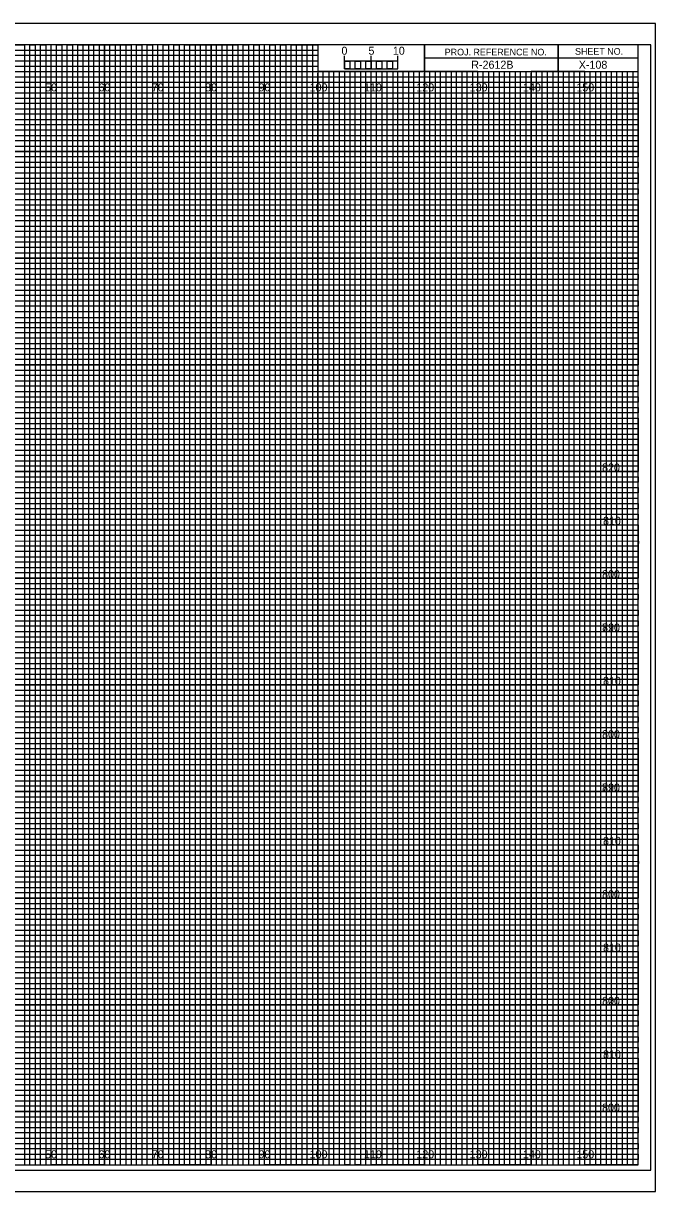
# Model space of a CAD drawing. Extents: x -13 to 323, y -5 to 214.
# Drawn here: x 204.8 to 323.3, y -5 to 214 of the extents above; entities that cross this region are included whole.
import ezdxf

# ---------------------------------------------------------------- set-up
doc = ezdxf.new("R2010")
doc.units = 0
for name, color, linetype in [('Prop XS Bar Scale Labels', 7, 'Continuous'), ('Prop XS Elevation Labels', 7, 'Continuous'), ('Prop XS Offset Labels', 7, 'Continuous'), ('Prop XS Project Number', 7, 'Continuous'), ('Prop XS Sheet Number', 7, 'Continuous'), ('Sheet Cross Section CELL', 7, 'Continuous'), ('Sheet Cross Section Grid Major CELL', 7, 'Continuous'), ('Sheet Cross Section Grid Middle CELL', 7, 'Continuous'), ('Sheet Cross Section Grid Minor 1 CELL', 7, 'Continuous'), ('Sheet Cross Section Grid Minor 2 CELL', 7, 'Continuous'), ('Sheet Cross Section Scale CELL', 7, 'Continuous'), ('Sheet Cutting Line CELL', 7, 'Continuous'), ('Sheet DOT Grid CELL', 7, 'Continuous'), ('Sheet Plot Border Inside CELL', 7, 'Continuous'), ('Sheet Plot Border Outside CELL', 7, 'Continuous')]:
    doc.layers.add(name, color=color, linetype=linetype)

msp = doc.modelspace()

# ---------------------------------------------------------------- linework, layer by layer
at = {"layer": 'Sheet Cross Section CELL'}
for p, q in [((305, 210), (305, 205)), ((305, 205), (305, 210)), ((280, 207.5), (280, 205)), ((320, 207.49), (280, 207.49)), ((280, 205), (320, 205))]:
    msp.add_line(p, q, dxfattribs=at)
for points in [[(320, 210), (0, 210), (0, 0), (320, 0)], [(280, 210), (260, 210), (260, 205.03), (280, 205.03)], [(320, 210), (280, 210), (280, 205), (320, 205)]]:
    msp.add_lwpolyline(points, close=True, dxfattribs=at)
at = {"layer": 'Sheet Cross Section Grid Major CELL'}
for p, q in [((210, 210), (200, 210)), ((210, 0), (210, 210)), ((230, 210), (220, 210)), ((220, 210), (220, 0)), ((230, 0), (230, 210)), ((250, 210), (240, 210)), ((240, 210), (240, 0)), ((250, 0), (250, 210)), ((260, 210), (260, 0)), ((270, 0), (270, 205)), ((290, 205), (280, 205)), ((280, 205), (280, 0)), ((290, 0), (290, 205)), ((310, 205), (300, 205)), ((300, 205), (300, 0)), ((310, 0), (310, 205)), ((220, 0), (210, 0)), ((240, 0), (230, 0)), ((260, 0), (250, 0)), ((280, 0), (270, 0)), ((300, 0), (290, 0)), ((320, 0), (310, 0)), ((320, 0), (320, 0))]:
    msp.add_line(p, q, dxfattribs=at)
for points in [[(0, 200), (320, 200), (320, 190), (0, 190)], [(0, 180), (320, 180), (320, 170), (0, 170)], [(0, 160), (320, 160), (320, 150), (0, 150)], [(0, 140), (320, 140), (320, 130), (0, 130)], [(0, 120), (320, 120), (320, 110), (0, 110)], [(0, 100), (320, 100), (320, 90), (0, 90)], [(0, 80), (320, 80), (320, 70), (0, 70)], [(0, 60), (320, 60), (320, 50), (0, 50)], [(0, 40), (320, 40), (320, 30), (0, 30)], [(0, 20), (320, 20), (320, 10), (0, 10)]]:
    msp.add_lwpolyline(points, dxfattribs=at)
at = {"layer": 'Sheet Cross Section Grid Middle CELL'}
for points in [[(195, 210), (205, 210), (205, 0), (215, 0), (215, 210), (225, 210), (225, 0), (235, 0), (235, 210), (245, 210), (245, 0), (255, 0), (255, 210), (259.93, 210), (260, 210), (260, 205), (264.99, 205), (264.99, 0), (275, 0), (275, 205), (285, 205), (285, 0), (295, 0), (295, 205), (305, 205), (305, 0), (315, 0), (315, 205)], [(0, 205), (275, 205)], [(0, 185), (320, 185), (320, 195), (0, 195)], [(0, 165), (320, 165), (320, 175), (0, 175)], [(0, 145), (320, 145), (320, 155), (0, 155)], [(0, 125), (320, 125), (320, 135), (0, 135)], [(0, 105), (320, 105), (320, 115), (0, 115)], [(0, 85), (320, 85), (320, 95), (0, 95)], [(0, 65), (320, 65), (320, 75), (0, 75)], [(0, 45), (320, 45), (320, 55), (0, 55)], [(0, 25), (320, 25), (320, 35), (0, 35)], [(0, 5), (320, 5), (320, 15), (0, 15)]]:
    msp.add_lwpolyline(points, dxfattribs=at)
at = {"layer": 'Sheet Cross Section Grid Minor 1 CELL'}
for p, q in [((0, 209), (260, 209)), ((260, 209), (260, 207.98)), ((260, 207.98), (0, 207.98)), ((0, 207), (260, 207)), ((260, 205.89), (0, 205.89)), ((260, 207), (260, 205.89)), ((0, 204), (320, 204))]:
    msp.add_line(p, q, dxfattribs=at)
for points in [[(0, 203), (270, 203), (320, 203), (320, 202), (0, 202)], [(0, 201), (320, 201), (320, 199), (0, 199)], [(0, 198), (320, 198), (320, 197), (0, 196.98)], [(0, 196), (320, 196), (320, 194), (0, 194)], [(0, 193), (320, 193), (320, 192), (0, 192)], [(0, 191), (320, 191), (320, 189), (0, 189)], [(0, 188), (320, 188), (320, 187), (0, 187)], [(0, 186), (320, 186), (320, 184), (0, 184)], [(0, 183), (320, 183), (320, 182), (0, 182)], [(0, 181), (320, 181), (320, 179), (0, 179)], [(0, 178), (320, 178), (320, 177), (0, 177)], [(0, 176), (320, 176), (320, 173.95), (320, 173), (320, 172), (0, 172)], [(0, 174), (320, 174), (320, 173), (0, 173)], [(0, 171), (320, 171), (320, 169), (0, 169.03)], [(0, 169.03), (320, 169), (320, 168), (0, 168)], [(0, 167), (320, 167), (320, 166), (0, 166)], [(0, 164), (320, 164), (320, 163), (0, 163)], [(0, 162), (320, 162), (320, 161), (0, 161)], [(-0.07, 158.89), (320, 158.89), (320, 157.88), (-0.07, 157.88)], [(0, 157), (320, 157), (320, 156), (0, 156)], [(0, 154), (320, 154), (320, 153), (0, 153)], [(0, 152), (320, 152), (320, 151), (0, 151)], [(0, 149), (320, 149), (320, 148), (0, 148)], [(0, 147), (320, 147), (320, 146), (0, 146)], [(0, 144), (320, 144), (320, 143), (0, 143)], [(0, 142), (320, 142), (320, 141), (0, 141)], [(0, 139), (320, 139), (319.99, 137.98), (0, 138)], [(0, 137), (320, 137), (320, 136), (0, 136)], [(0, 134), (320, 134), (320, 133), (0, 133)], [(0, 132), (320, 132), (320, 131), (0, 131)], [(0, 129), (320, 129), (320, 128), (0, 128)], [(0, 127), (320, 127), (320, 126), (0, 126)], [(0, 124), (320, 124), (320, 123), (0, 123)], [(0, 122), (320, 122), (320, 121), (0, 121)], [(0, 119), (320, 119), (320, 118), (0, 118)], [(0, 116.99), (320.07, 116.91), (320, 116), (0, 116)], [(0, 114), (320, 114), (320, 113), (0, 113)], [(0, 112), (320, 112), (320, 111), (0, 111)], [(0, 109), (320, 109), (320, 108), (0, 108)], [(0, 107), (320, 107), (320, 106), (0, 106)], [(0, 104), (320, 104), (320, 103), (0, 103)], [(0, 102), (320, 102), (320, 101), (0, 101)], [(0, 99), (320, 99), (320, 98), (0, 98)], [(0, 97), (320, 97), (320, 96), (0, 96)], [(0, 94), (320, 94), (320, 93), (0, 93)], [(0, 92), (320, 92), (320, 91), (0, 91)], [(0, 89), (320, 89), (320, 88), (0, 88)], [(0, 87), (320, 87), (320, 86), (0, 86)], [(0, 84), (320, 84), (320, 83), (0, 83)], [(0, 82), (320, 82), (320, 81), (0, 81)], [(0, 79), (320, 79), (319.99, 77.98), (0, 78)], [(0, 77), (320, 77), (320, 76), (0, 76)], [(0, 74), (320, 74), (320, 73), (0, 73)], [(0, 72), (320, 72), (320, 71), (0, 71)], [(0, 69), (320, 69), (320, 68), (0, 68)], [(0, 67), (320, 67), (320, 66), (0, 66)], [(0, 64), (320, 64), (320, 63), (0, 63)], [(0, 62), (320, 62), (320, 61), (0, 61)], [(0, 59), (320, 59), (320, 58), (0, 58)], [(0, 56.99), (320.07, 56.91), (320, 56), (0, 56)], [(0, 54), (320, 54), (320, 53), (0, 53)], [(0, 52), (320, 52), (320, 51), (0, 51)], [(0, 49), (320, 49), (320, 48), (0, 48)], [(0, 47), (320, 47), (320, 46), (0, 46)], [(0, 44), (320, 44), (320, 43), (0, 43)], [(0, 42), (320, 42), (320, 41), (0, 41)], [(0, 39), (320, 39), (320, 38), (0, 38)], [(0, 37), (320, 37), (320, 36), (0, 36)], [(0, 34), (320, 34), (320, 33), (0, 33)], [(0, 32), (320, 32), (320, 31), (0, 31)], [(0, 29), (320, 29), (320, 28), (0, 28)], [(0, 27), (320, 27), (320, 26), (0, 26)], [(0, 24), (320, 24), (320, 23), (0, 23)], [(0, 22), (320, 22), (320, 21), (0, 21)], [(0, 19), (320, 19), (320, 18), (0, 18)], [(0, 17), (320, 17), (320, 16), (0, 16)], [(0, 14), (320, 14), (320, 13), (0, 13)], [(0, 12), (320, 12), (320, 11), (0, 11)], [(0, 9), (320, 9), (320, 8), (0, 8)], [(0, 7), (320, 7), (320, 6), (0, 6)], [(0, 4), (320, 4), (320, 3), (0, 3)], [(0, 2), (320, 2), (320, 1), (0, 1)]]:
    msp.add_lwpolyline(points, dxfattribs=at)
at = {"layer": 'Sheet Cross Section Grid Minor 2 CELL'}
for p, q in [((267, 205), (266.01, 205)), ((266.01, 205), (266.01, 0)), ((267, 0), (267, 205)), ((269, 205), (268, 205)), ((268, 205), (268, 0)), ((269, 0), (269, 205)), ((266.01, 0), (265, 0)), ((268, 0), (267, 0))]:
    msp.add_line(p, q, dxfattribs=at)
for points in [[(205, 0), (206, 0), (206, 210), (207, 210), (207, 0)], [(207, 0), (208, 0), (208, 210), (209, 210), (209, 0)], [(210, 0), (211, 0), (211, 210), (212, 210), (212, 0)], [(212, 0), (213, 0), (213, 210), (214, 210), (214, 0)], [(215, 0), (216, 0), (216, 210), (217, 210), (217, 0)], [(217, 0), (218, 0), (218, 210), (219, 210), (219, 0)], [(220, 0), (221, 0), (221, 210), (222, 210), (222, 0)], [(222, 0), (223, 0), (223, 210), (224, 210), (224, 0)], [(225, 0), (226, 0), (226, 210), (227, 210), (227, 0)], [(227, 0), (228, 0), (228, 210), (229, 210), (229, 0)], [(230, 0), (231, 0), (231, 210), (232, 210), (232, 0)], [(232, 0), (233, 0), (233, 210), (234, 210), (234, 0)], [(235, 0), (236, 0), (236, 210), (237, 210), (237, 0)], [(237, 0), (238, 0), (238, 210), (239, 210), (239, 0)], [(240, 0), (241, 0), (241, 210), (242, 210), (242, 0)], [(242, 0), (243, 0), (243, 210), (244, 210), (244, 0)], [(245, 0), (246, 0), (246, 210), (247, 210), (247, 0)], [(247, 0), (248, 0), (248, 210), (249, 210), (249, 0)], [(250, 0), (251, 0), (251, 210), (252, 210), (252, 0)], [(252, 0), (253, 0), (253, 210), (254, 210), (254, 0)], [(255, 0), (256, 0), (256, 210), (257, 210), (257, 0)], [(257, 0), (258, 0), (258, 210), (259, 210), (259, 0)], [(260, 0), (261, 0), (261, 205), (262.02, 205), (262.02, 0)], [(262, 0), (263, 0), (263, 205), (263.99, 205), (263.99, 0)], [(270, 0), (270.98, 0), (270.98, 205), (272, 205), (272, 0)], [(272, 0), (273, 0), (273, 205), (274.05, 205), (274.05, 0)], [(275, 0), (276, 0), (276, 205), (277, 205), (277, 0)], [(277, 0), (278, 0), (278, 205), (279, 205), (279, 0)], [(280, 0), (281, 0), (281, 205), (282, 205), (282, 0)], [(282, 0), (283, 0), (283, 205), (284, 205), (284, 0)], [(285, 0), (286, 0), (286, 205), (287, 205), (287, 0)], [(287, 0), (288, 0), (288, 205), (289, 205), (289, 0)], [(290, 0), (291, 0), (291, 205), (292, 205), (292, 0)], [(292, 0), (293, 0), (293, 205), (294, 205), (294, 0)], [(295, 0), (296, 0), (296, 205), (297, 205), (297, 0)], [(297, 0), (298, 0), (298, 205), (299, 205), (299, 0)], [(300, 0), (301, 0), (301, 205), (302, 205), (302, 0)], [(302, 0), (303, 0), (303, 205), (304, 205), (304, 0)], [(305, 0), (306, 0), (306, 205), (307, 205), (307, 0)], [(307, 0), (308, 0), (308, 205), (309, 205), (309, 0)], [(310, 0), (311, 0), (311, 205), (312, 205), (312, 0)], [(312, 0), (313, 0), (313, 205), (314, 205), (314, 0)], [(315, 0), (316, 0), (316, 205), (317, 205), (317, 0)], [(317, 0), (318, 0), (318, 205), (319, 205), (319, 0)]]:
    msp.add_lwpolyline(points, dxfattribs=at)
at = {"layer": 'Sheet Cross Section Scale CELL'}
for p, q in [((265, 205.49), (265, 207.9)), ((265, 206.9), (265, 207.9)), ((270, 205.49), (270, 207.9)), ((275, 205.49), (275, 207.9)), ((275, 206.9), (275, 207.9))]:
    msp.add_line(p, q, dxfattribs=at)
for points in [[(275, 206.9), (265, 206.9), (265, 205.49), (275, 205.49)], [(265, 206.9), (266, 206.9), (266, 205.49), (265, 205.49)], [(267, 206.9), (268, 206.9), (268, 205.49), (267, 205.49)], [(269, 206.9), (270, 206.9), (270, 205.49), (269, 205.49)], [(271, 206.9), (272, 206.9), (272, 205.49), (271, 205.49)], [(273, 206.9), (274, 206.9), (274, 205.49), (273, 205.49)]]:
    msp.add_lwpolyline(points, close=True, dxfattribs=at)
at = {"layer": 'Sheet Cutting Line CELL'}
for p, q in [((323.3, 214), (-13.4, 214)), ((-13.4, -5), (323.3, -5))]:
    msp.add_line(p, q, dxfattribs=at)
at = {"layer": 'Sheet DOT Grid CELL'}
for p, q in [((210, 0), (210, 210)), ((220, 0), (220, 210)), ((230, 0), (230, 210)), ((240, 0), (240, 210)), ((250, 0), (250, 210)), ((260, 0), (260, 204.69)), ((270, 0), (270, 204.69)), ((280, 0), (280, 204.69)), ((290, 0), (290, 204.69)), ((300, 0), (300, 204.69)), ((310, 0), (310, 204.69)), ((0, 200), (320, 200)), ((0, 190), (320, 190)), ((0, 180), (320, 180)), ((0, 170), (320, 170)), ((0, 160), (320, 160)), ((0, 150), (320, 150)), ((0, 140), (320, 140)), ((0, 130), (320, 130)), ((0, 120), (320, 120)), ((0, 110), (320, 110)), ((0, 100), (320, 100)), ((0, 90), (320, 90)), ((0, 80), (320, 80)), ((0, 70), (320, 70)), ((0, 60), (320, 60)), ((0, 50), (320, 50)), ((0, 40), (320, 40)), ((0, 30), (320, 30)), ((0, 20), (320, 20)), ((0, 10), (320, 10))]:
    msp.add_line(p, q, dxfattribs=at)
at = {"layer": 'Sheet Plot Border Inside CELL'}
msp.add_lwpolyline([(-10.8, -1), (322.4, -1), (322.4, 210), (-10.8, 210)], close=True, dxfattribs=at)
at = {"layer": 'Sheet Plot Border Outside CELL'}
msp.add_lwpolyline([(-13.4, -5), (323.3, -5), (323.3, 214), (-13.4, 214)], close=True, dxfattribs=at)

# ---------------------------------------------------------------- texts
at = {"layer": 'Prop XS Bar Scale Labels'}
for s, p in [('5', (269.47, 208.12)), ('10', (274.04, 208.12))]:
    msp.add_text(s, height=1.5, dxfattribs=at).set_placement(p)
at = {"layer": 'Prop XS Elevation Labels'}
for s, p in [('820', (313.26, 130)), ('810', (313.44, 120)), ('800', (313.26, 110)), ('820', (313.26, 100)), ('790', (313.26, 100)), ('810', (313.44, 90)), ('800', (313.26, 80)), ('820', (313.26, 70)), ('790', (313.26, 70)), ('810', (313.44, 60)), ('800', (313.26, 50)), ('810', (313.44, 40)), ('820', (313.26, 30)), ('800', (313.26, 30)), ('810', (313.44, 20)), ('800', (313.26, 10))]:
    msp.add_text(s, height=1.5, dxfattribs=at).set_placement(p)
at = {"layer": 'Prop XS Offset Labels'}
for s, p in [('50', (208.86, 201.25)), ('60', (218.86, 201.25)), ('70', (228.86, 201.25)), ('80', (238.86, 201.25)), ('90', (248.86, 201.25)), ('100', (258.44, 201.25)), ('110', (268.62, 201.25)), ('120', (278.44, 201.25)), ('130', (288.44, 201.25)), ('140', (298.44, 201.25)), ('150', (308.44, 201.25)), ('50', (208.86, 1.25)), ('60', (218.86, 1.25)), ('70', (228.86, 1.25)), ('80', (238.86, 1.25)), ('90', (248.86, 1.25)), ('100', (258.44, 1.25)), ('110', (268.62, 1.25)), ('120', (278.44, 1.25)), ('130', (288.44, 1.25)), ('140', (298.44, 1.25)), ('150', (308.44, 1.25))]:
    msp.add_text(s, height=1.5, dxfattribs=at).set_placement(p)
at = {"layer": 'Prop XS Project Number'}
msp.add_text('R-2612B', height=1.5, dxfattribs=at).set_placement((288.74, 205.5))
at = {"layer": 'Prop XS Sheet Number'}
msp.add_text('X-108', height=1.5, dxfattribs=at).set_placement((308.89, 205.5))
at = {"layer": 'Sheet Cross Section CELL'}
for s, p in [('PROJ. REFERENCE NO.', (283.77, 207.99)), ('SHEET NO.', (308.19, 208.12))]:
    msp.add_text(s, height=1.25, dxfattribs=at).set_placement(p)
at = {"layer": 'Sheet Cross Section Scale CELL'}
msp.add_text('0', height=1.5, dxfattribs=at).set_placement((264.41, 208.12))

doc.saveas('drawing.dxf')
